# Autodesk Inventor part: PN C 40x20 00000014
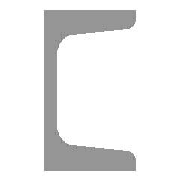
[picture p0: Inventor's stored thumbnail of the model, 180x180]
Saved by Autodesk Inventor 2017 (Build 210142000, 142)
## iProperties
_CCFamilyMember: 10
_CCFamilyDisplayName: PN-86/H-93403 - Ceownik
_FrameMemberDoc: Frame Member File
_Version: 15.0.0
_GetPNFromCC: 1
Created: 2016-02
Part Number: PN C 40x20 00000014
Material: Stal, miękka
Description: Ceownik
Document SubType Name: Modeling
Standard: PN
Designer: X
Standards Organization: PN
Language: pl-PL
Size Designation: C 35x35
Categories: <MemberInstance><Categories><Category DisplayName="Kształtowniki konstrukcyjne" InternalName="089c4875-fa83-4c05-b084-43b9cc11f5ed" Mnemonic="GRDR"><CategoryPar
Stock Number: C 35x35
Density: 7.85 g/cm^3
Appearance: Częściowo polerowana
IsCustomPart: 1
G_L: 1940,000 mm
G_W: 35,000 mm
G_H: 35,000 mm
Author: X
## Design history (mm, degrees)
node "Płaszczyzna początkowa"
node "Płaszczyzna końcowa"
sketch "Szkic"
  geometry: L1 (0, 0)-(0, 17.5); L2 (0, 17.5)-(35, 17.5); L3 (35, 17.5)-(35, 15.47); L4 (32.239, 12.479)-(10.522, 10.742); L5 (5, 4.761)-(5, 0); L6 (5, 0)-(0, 0); L7 (20, 17.5)-(20, 11.5); L8 (35, 12.7)-(35, 11.5); L9 (35, 11.5)-(20, 11.5); L10 (0, 15)-(0, -27); L11 (-5.539, 0)-(16.007, 0); L12 (0, 0)-(0, -17.5); L13 (0, -17.5)-(35, -17.5); L14 (35, -17.5)-(35, -15.47); L15 (32.239, -12.479)-(10.522, -10.742); L16 (5, -4.761)-(5, 0); L17 (0, 26.4)-(0, -35.9) reference; L18 (-13.764, 0)-(43.809, 0) reference; A1 r 6 centre (11, 4.761) between (10.522, 10.742) and (5, 4.761); A2 r 6 centre (11, -4.761) between (5, -4.761) and (10.522, -10.742); A3 r 3 centre (32, 15.47) between (32.239, 12.479) and (35, 15.47); A4 r 3 centre (32, -15.47) between (35, -15.47) and (32.239, -12.479); 5 further points
  constraints: 32 end point, 12 point on line, 8 point on circle, 8 tangent, 6 symmetric about line, 4 centre point, 4 parallel, 3 collinear, 3 perpendicular, 2 equal radius, 5 other
  dimensions: "d0" = 5 distance between parallel lines of L1 L5 (= G_T); "d1" = 17.5 distance between parallel lines of L6 L2 (= 0.5 x G_H); "d2" = 35 distance between parallel lines of L3 L1 (= G_W); "d3" = 6 distance of L2.end L8.end (= G_T1); "d4" = 15 distance of L7.start L2.end (= G_C); "d5" = 1.2 distance of L8.start L8.end (computed from G_NG, G_C); "d23" = 6 radius of A1 (= G_IR); "d24" = 3 radius of A3 (= G_ER); "d25" = 0 distance between parallel lines of L10 L12 (computed from ex)
extrude "Bryła" new body sketch "Szkic" stored distance "d6" = 1940 (= G_L); taper "d7" = 0 deg
node "Driven Length"
  sketch "Sketch3"
    geometry: L1 (0, 0)-(10, 0) reference
    constraints: 2 end point, 1 horizontal
  workplane "Work Plane3"
  sketch "Sketch4"
    geometry: L1 (-2, 0)-(12, 0) reference; L2 (-2, 1940)-(12, 1940) reference
    dimensions: "d29" = 1940 distance between parallel lines of L1 L2 (derived)
body "Solid1"
other parameters: "G_W" = 35 [user parameter; used in 1 equation term], "G_H" = 35 [user parameter; used in 1 equation term], "G_T" = 5 [user parameter; used in 1 equation term], "G_T1" = 6 [user parameter; used in 1 equation term], "G_NG" = 0.8 [user parameter; used in 1 equation term], "G_ER" = 3 [user parameter; used in 1 equation term], "G_IR" = 6 [user parameter; used in 1 equation term], "G_C" = 15 [user parameter; used in 2 equation terms], "G_L" = 1940 (= d29) [user parameter; used in 1 equation term], "ex" = 0 [user parameter; used in 1 equation term], "G_OFFSET_START" = 0 [user parameter; used in 1 equation term], "G_OFFSET_END" = 0 [user parameter; used in 1 equation term], "d26" = 0 (computed from G_OFFSET_START), "d28" = 90 deg
